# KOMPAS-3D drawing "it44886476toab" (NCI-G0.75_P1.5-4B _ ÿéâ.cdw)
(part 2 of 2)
  Кривая без истории:10773
  Кривая без истории:10774
  Кривая без истории:10775
  Кривая без истории:10776
  Кривая без истории:10777
  Кривая без истории:10778
  Кривая без истории:10779
  Кривая без истории:10780
  Кривая без истории:10781
  Кривая без истории:10782
  Кривая без истории:10783
  Кривая без истории:10784
  Кривая без истории:10785
  Кривая без истории:10786
  Кривая без истории:10787
  Кривая без истории:10788
  Кривая без истории:10789
  Кривая без истории:10790
  Кривая без истории:10791
  Кривая без истории:10792
  Кривая без истории:10793
  Кривая без истории:10794
  Кривая без истории:10795
  Кривая без истории:10796
  Кривая без истории:10797
  Кривая без истории:10798
  Кривая без истории:10799
  Кривая без истории:10800
  Кривая без истории:10801
  Кривая без истории:10802
  Кривая без истории:10803
  Кривая без истории:10804
  Кривая без истории:10805
  Кривая без истории:10806
  Кривая без истории:10807
  Кривая без истории:10808
  Кривая без истории:10809
  Кривая без истории:10810
  Кривая без истории:10811
  Кривая без истории:10812
  Кривая без истории:10813
  Кривая без истории:10814
  Кривая без истории:10815
  Кривая без истории:10816
  Кривая без истории:10817
  Кривая без истории:10818
  Кривая без истории:10819
  Кривая без истории:10820
  Кривая без истории:10821
  Кривая без истории:10822
  Кривая без истории:10823
  Кривая без истории:10824
  Кривая без истории:10825
  Кривая без истории:10826
  Кривая без истории:10827
  Кривая без истории:10828
  Кривая без истории:10829
  Кривая без истории:10830
  Кривая без истории:10831
  Кривая без истории:10832
  Кривая без истории:10833
  Кривая без истории:10834
  Кривая без истории:10835
  Кривая без истории:10836
  Кривая без истории:10837
  Кривая без истории:10838
  Кривая без истории:10839
  Кривая без истории:10840
  Кривая без истории:10841
  Кривая без истории:10842
  Кривая без истории:10843
  Кривая без истории:10844
  Кривая без истории:10845
  Кривая без истории:10846
  Кривая без истории:10847
  Кривая без истории:10848
  Кривая без истории:10849
  Кривая без истории:10850
  Кривая без истории:10851
  Кривая без истории:10852
  Кривая без истории:10853
  Кривая без истории:10854
  Кривая без истории:10855
  Кривая без истории:10856
  Кривая без истории:10857
  Кривая без истории:10858
  Кривая без истории:10859
  Кривая без истории:10860
  Кривая без истории:10861
  Кривая без истории:10862
  Кривая без истории:10863
  Кривая без истории:10864
  Кривая без истории:10865
  Кривая без истории:10866
  Кривая без истории:10867
  Кривая без истории:10868
  Кривая без истории:10869
  Кривая без истории:10870
  Кривая без истории:10871
  Кривая без истории:10872
  Кривая без истории:10873
  Кривая без истории:10874
  Кривая без истории:10875
  Кривая без истории:10876
  Кривая без истории:10877
  Кривая без истории:10878
  Кривая без истории:10879
  Кривая без истории:10880
  Кривая без истории:10881
  Кривая без истории:10882
  Кривая без истории:10883
  Кривая без истории:10884
  Кривая без истории:10885
  Кривая без истории:10886
  Кривая без истории:10887
  Кривая без истории:10888
  Кривая без истории:10889
  Кривая без истории:10890
  Кривая без истории:10891
  Кривая без истории:10892
  Кривая без истории:10893
  Кривая без истории:10894
  Кривая без истории:10895
  Кривая без истории:10896
  Кривая без истории:10897
  Кривая без истории:10898
  Кривая без истории:10899
  Кривая без истории:10900
  Кривая без истории:10901
  Кривая без истории:10902
  Кривая без истории:10903
  Кривая без истории:10904
  Кривая без истории:10905
  Кривая без истории:10906
  Кривая без истории:10907
  Кривая без истории:10908
  Кривая без истории:10909
  Кривая без истории:10910
  Кривая без истории:10911
  Кривая без истории:10912
  Кривая без истории:10913
  Кривая без истории:10914
  Кривая без истории:10915
  Кривая без истории:10916
  Кривая без истории:10917
  Кривая без истории:10918
  Кривая без истории:10919
  Кривая без истории:10920
  Кривая без истории:10921
  Кривая без истории:10922
  Кривая без истории:10923
  Кривая без истории:10924
  Кривая без истории:10925
  Кривая без истории:10926
  Кривая без истории:10927
  Кривая без истории:10928
  Кривая без истории:10929
  Кривая без истории:10930
  Кривая без истории:10931
  Кривая без истории:10932
  Кривая без истории:10933
  Кривая без истории:10934
  Кривая без истории:10935
  Кривая без истории:10936
  Кривая без истории:10937
  Кривая без истории:10938
  Кривая без истории:10939
  Кривая без истории:10940
  Кривая без истории:10941
  Кривая без истории:10942
  Кривая без истории:10943
  Кривая без истории:10944
  Кривая без истории:10945
  Кривая без истории:10946
  Кривая без истории:10947
  Кривая без истории:10948
  Кривая без истории:10949
  Кривая без истории:10950
  Кривая без истории:10951
  Кривая без истории:10952
  Кривая без истории:10953
  Кривая без истории:10954
  Кривая без истории:10955
  Кривая без истории:10956
  Кривая без истории:10957
  Кривая без истории:10958
  Кривая без истории:10959
  Кривая без истории:10960
  Кривая без истории:10961
  Кривая без истории:10962
  Кривая без истории:10963
  Кривая без истории:10964
  Кривая без истории:10965
  Кривая без истории:10966
  Кривая без истории:10967
  Кривая без истории:10968
  Кривая без истории:10969
  Кривая без истории:10970
  Кривая без истории:10971
  Кривая без истории:10972
  Кривая без истории:10973
  Кривая без истории:10974
  Кривая без истории:10975
  Кривая без истории:10976
  Кривая без истории:10977
  Кривая без истории:10978
  Кривая без истории:10979
  Кривая без истории:10980
  Кривая без истории:10981
  Кривая без истории:10982
  Кривая без истории:10983
  Кривая без истории:10984
  Кривая без истории:10985
  Кривая без истории:10986
  Кривая без истории:10987
  Кривая без истории:10988
  Кривая без истории:10989
  Кривая без истории:10990
  Кривая без истории:10991
  Кривая без истории:10992
  Кривая без истории:10993
  Кривая без истории:10994
  Кривая без истории:10995
  Кривая без истории:10996
  Кривая без истории:10997
  Кривая без истории:10998
  Кривая без истории:10999
  Кривая без истории:11000
  Кривая без истории:11001
  Кривая без истории:11002
  Кривая без истории:11003
  Кривая без истории:11004
  Кривая без истории:11005
  Кривая без истории:11006
  Кривая без истории:11007
  Кривая без истории:11008
  Кривая без истории:11009
  Кривая без истории:11010
  Кривая без истории:11011
  Кривая без истории:11012
  Кривая без истории:11013
  Кривая без истории:11014
  Кривая без истории:11015
  Кривая без истории:11016
  Кривая без истории:11017
  Кривая без истории:11018
  Кривая без истории:11019
  Кривая без истории:11020
  Кривая без истории:11021
  Кривая без истории:11022
  Кривая без истории:11023
  Кривая без истории:11024
  Кривая без истории:11025
  Кривая без истории:11026
  Кривая без истории:11027
  Кривая без истории:11028
  Кривая без истории:11029
  Кривая без истории:11030
  Кривая без истории:11031
  Кривая без истории:11032
  Кривая без истории:11033
  Кривая без истории:11034
  Кривая без истории:11035
  Кривая без истории:11036
  Кривая без истории:11037
  Кривая без истории:11038
  Кривая без истории:11039
  Кривая без истории:11040
  Кривая без истории:11041
  Кривая без истории:11042
  Кривая без истории:11043
  Кривая без истории:11044
  Кривая без истории:11045
  Кривая без истории:11046
  Кривая без истории:11047
  Кривая без истории:11048
  Кривая без истории:11049
  Кривая без истории:11050
  Кривая без истории:11051
  Кривая без истории:11052
  Кривая без истории:11053
  Кривая без истории:11054
  Кривая без истории:11055
  Кривая без истории:11056
  Кривая без истории:11057
  Кривая без истории:11058
  Кривая без истории:11059
  Кривая без истории:11060
  Кривая без истории:11061
  Кривая без истории:11062
  Кривая без истории:11063
  Кривая без истории:11064
  Кривая без истории:11065
  Кривая без истории:11066
  Кривая без истории:11067
  Кривая без истории:11068
  Кривая без истории:11069
  Кривая без истории:11070
  Кривая без истории:11071
  Кривая без истории:11072
  Кривая без истории:11073
  Кривая без истории:11074
  Кривая без истории:11075
  Кривая без истории:11076
  Кривая без истории:11077
  Кривая без истории:11078
  Кривая без истории:11079
  Кривая без истории:11080
  Кривая без истории:11081
  Кривая без истории:11082
  Кривая без истории:11083
  Кривая без истории:11084
  Кривая без истории:11085
  Кривая без истории:11086
  Кривая без истории:11087
  Кривая без истории:11088
  Кривая без истории:11089
  Кривая без истории:11090
  Кривая без истории:11091
  Кривая без истории:11092
  Кривая без истории:11093
  Кривая без истории:11094
  Кривая без истории:11095
  Кривая без истории:11096
  Кривая без истории:11097
  Кривая без истории:11098
  Кривая без истории:11099
  Кривая без истории:11100
  Кривая без истории:11101
  Кривая без истории:11102
  Кривая без истории:11103
  Кривая без истории:11104
  Кривая без истории:11105
  Кривая без истории:11106
  Кривая без истории:11107
  Кривая без истории:11108
  Кривая без истории:11109
  Кривая без истории:11110
  Кривая без истории:11111
  Кривая без истории:11112
  Кривая без истории:11113
  Кривая без истории:11114
  Кривая без истории:11115
  Кривая без истории:11116
  Кривая без истории:11117
  Кривая без истории:11118
  Кривая без истории:11119
  Кривая без истории:11120
  Кривая без истории:11121
  Кривая без истории:11122
  Кривая без истории:11123
  Кривая без истории:11124
  Кривая без истории:11125
  Кривая без истории:11126
  Кривая без истории:11127
  Кривая без истории:11128
  Кривая без истории:11129
  Кривая без истории:11130
  Кривая без истории:11131
  Кривая без истории:11132
  Кривая без истории:11133
  Кривая без истории:11134
  Кривая без истории:11135
  Кривая без истории:11136
  Кривая без истории:11137
  Кривая без истории:11138
  Кривая без истории:11139
  Кривая без истории:11140
  Кривая без истории:11141
  Кривая без истории:11142
  Кривая без истории:11143
  Кривая без истории:11144
  Кривая без истории:11145
  Кривая без истории:11146
  Кривая без истории:11147
  Кривая без истории:11148
  Кривая без истории:11149
  Кривая без истории:11150
  Кривая без истории:11151
  Кривая без истории:11152
  Кривая без истории:11153
  Кривая без истории:11154
  Кривая без истории:11155
  Кривая без истории:11156
  Кривая без истории:11157
  Кривая без истории:11158
  Кривая без истории:11159
  Кривая без истории:11160
  Кривая без истории:11161
  Кривая без истории:11162
  Кривая без истории:11163
  Кривая без истории:11164
  Кривая без истории:11165
  Кривая без истории:11166
  Кривая без истории:11167
  Кривая без истории:11168
  Кривая без истории:11169
  Кривая без истории:11170
  Кривая без истории:11171
  Кривая без истории:11172
  Кривая без истории:11173
  Кривая без истории:11174
  Кривая без истории:11175
  Кривая без истории:11176
  Кривая без истории:11177
  Кривая без истории:11178
  Кривая без истории:11179
  Кривая без истории:11180
  Кривая без истории:11181
  Кривая без истории:11182
  Кривая без истории:11183
  Кривая без истории:11184
  Кривая без истории:11185
  Кривая без истории:11186
  Кривая без истории:11187
  Кривая без истории:11188
  Кривая без истории:11189
  Кривая без истории:11190
  Кривая без истории:11191
  Кривая без истории:11192
  Кривая без истории:11193
  Кривая без истории:11194
  Кривая без истории:11195
  Кривая без истории:11196
  Кривая без истории:11197
  Кривая без истории:11198
  Кривая без истории:11199
  Кривая без истории:11200
  Кривая без истории:11201
  Кривая без истории:11202
  Кривая без истории:11203
  Кривая без истории:11204
  Кривая без истории:11205
  Кривая без истории:11206
  Кривая без истории:11207
  Кривая без истории:11208
  Кривая без истории:11209
  Кривая без истории:11210
  Кривая без истории:11211
  Кривая без истории:11212
  Кривая без истории:11213
  Кривая без истории:11214
  Кривая без истории:11215
  Кривая без истории:11216
  Кривая без истории:11217
  Кривая без истории:11218
  Кривая без истории:11219
  Кривая без истории:11220
  Кривая без истории:11221
  Кривая без истории:11222
  Кривая без истории:11223
  Кривая без истории:11224
  Кривая без истории:11225
  Кривая без истории:11226
  Кривая без истории:11227
  Кривая без истории:11228
  Кривая без истории:11229
  Кривая без истории:11230
  Кривая без истории:11231
  Кривая без истории:11232
  Кривая без истории:11233
  Кривая без истории:11234
  Кривая без истории:11235
  Кривая без истории:11236
  Кривая без истории:11237
  Кривая без истории:11238
  Кривая без истории:11239
  Кривая без истории:11240
  Кривая без истории:11241
  Кривая без истории:11242
  Кривая без истории:11243
  Кривая без истории:11244
  Кривая без истории:11245
  Кривая без истории:11246
  Кривая без истории:11247
  Кривая без истории:11248
  Кривая без истории:11249
  Кривая без истории:11250
  Кривая без истории:11251
  Кривая без истории:11252
  Кривая без истории:11253
  Кривая без истории:11254
  Кривая без истории:11255
  Кривая без истории:11256
  Кривая без истории:11257
  Кривая без истории:11258
  Кривая без истории:11259
  Кривая без истории:11260
  Кривая без истории:11261
  Кривая без истории:11262
  Кривая без истории:11263
  Кривая без истории:11264
  Кривая без истории:11265
  Кривая без истории:11266
  Кривая без истории:11267
  Кривая без истории:11268
  Кривая без истории:11269
  Кривая без истории:11270
  Кривая без истории:11271
  Кривая без истории:11272
  Кривая без истории:11273
  Кривая без истории:11274
  Кривая без истории:11275
  Кривая без истории:11276
  Кривая без истории:11277
  Кривая без истории:11278
  Кривая без истории:11279
  Кривая без истории:11280
  Кривая без истории:11281
  Кривая без истории:11282
  Кривая без истории:11283
  Кривая без истории:11284
  Кривая без истории:11285
  Кривая без истории:11286
  Кривая без истории:11287
  Кривая без истории:11288
  Кривая без истории:11289
  Кривая без истории:11290
  Кривая без истории:11291
  Кривая без истории:11292
  Кривая без истории:11293
  Кривая без истории:11294
  Кривая без истории:11295
  Кривая без истории:11296
  Кривая без истории:11297
  Кривая без истории:11298
  Кривая без истории:11299
  Кривая без истории:11300
  Кривая без истории:11301
  Кривая без истории:11302
  Кривая без истории:11303
  Кривая без истории:11304
  Кривая без истории:11305
  Кривая без истории:11306
  Кривая без истории:11307
  Кривая без истории:11308
  Кривая без истории:11309
  Кривая без истории:11310
  Кривая без истории:11311
  Кривая без истории:11312
  Кривая без истории:11313
  Кривая без истории:11314
  Кривая без истории:11315
  Кривая без истории:11316
  Кривая без истории:11317
  Кривая без истории:11318
  Кривая без истории:11319
  Кривая без истории:11320
  Кривая без истории:11321
  Кривая без истории:11322
  Кривая без истории:11323
  Кривая без истории:11324
  Кривая без истории:11325
  Кривая без истории:11326
  Кривая без истории:11327
  Кривая без истории:11328
  Кривая без истории:11329
  Кривая без истории:11330
  Кривая без истории:11331
  Кривая без истории:11332
  Кривая без истории:11333
  Кривая без истории:11334
  Кривая без истории:11335
  Кривая без истории:11336
  Кривая без истории:11337
  Кривая без истории:11338
  Кривая без истории:11339
  Кривая без истории:11340
  Кривая без истории:11341
  Кривая без истории:11342
  Кривая без истории:11343
  Кривая без истории:11344
  Кривая без истории:11345
  Кривая без истории:11346
  Кривая без истории:11347
  Кривая без истории:11348
  Кривая без истории:11349
  Кривая без истории:11350
  Кривая без истории:11351
  Кривая без истории:11352
  Кривая без истории:11353
  Кривая без истории:11354
  Кривая без истории:11355
  Кривая без истории:11356
  Кривая без истории:11357
  Кривая без истории:11358
  Кривая без истории:11359
  Кривая без истории:11360
  Кривая без истории:11361
  Кривая без истории:11362
  Кривая без истории:11363
  Кривая без истории:11364
  Кривая без истории:11365
  Кривая без истории:11366
  Кривая без истории:11367
  Кривая без истории:11368
  Кривая без истории:11369
  Кривая без истории:11370
  Кривая без истории:11371
  Кривая без истории:11372
  Кривая без истории:11373
  Кривая без истории:11374
  Кривая без истории:11375
  Кривая без истории:11376
  Кривая без истории:11377
  Кривая без истории:11378
  Кривая без истории:11379
  Кривая без истории:11380
  Кривая без истории:11381
  Кривая без истории:11382
  Кривая без истории:11383
  Кривая без истории:11384
  Кривая без истории:11385
  Кривая без истории:11386
  Кривая без истории:11387
  Кривая без истории:11388
  Кривая без истории:11389
  Кривая без истории:11390
  Кривая без истории:11391
  Кривая без истории:11392
  Кривая без истории:11393
  Кривая без истории:11394
  Кривая без истории:11395
  Кривая без истории:11396
  Кривая без истории:11397
  Кривая без истории:11398
  Кривая без истории:11399
  Кривая без истории:11400
  Кривая без истории:11401
  Кривая без истории:11402
  Кривая без истории:11403
  Кривая без истории:11404
  Кривая без истории:11405
  Кривая без истории:11406
  Кривая без истории:11407
  Кривая без истории:11408
  Кривая без истории:11409
  Кривая без истории:11410
  Кривая без истории:11411
  Кривая без истории:11412
  Кривая без истории:11413
  Кривая без истории:11414
  Кривая без истории:11415
  Кривая без истории:11416
  Кривая без истории:11417
  Кривая без истории:11418
  Кривая без истории:11419
  Кривая без истории:11420
  Кривая без истории:11421
  Кривая без истории:11422
  Кривая без истории:11423
  Кривая без истории:11424
  Кривая без истории:11425
  Кривая без истории:11426
  Кривая без истории:11427
  Кривая без истории:11428
  Кривая без истории:11429
  Кривая без истории:11430
  Кривая без истории:11431
  Кривая без истории:11432
  Кривая без истории:11433
  Кривая без истории:11434
  Кривая без истории:11435
  Кривая без истории:11436
  Кривая без истории:11437
  Кривая без истории:11438
  Кривая без истории:11439
  Кривая без истории:11440
  Кривая без истории:11441
  Кривая без истории:11442
  Кривая без истории:11443
  Кривая без истории:11444
  Кривая без истории:11445
  Кривая без истории:11446
  Кривая без истории:11447
  Кривая без истории:11448
  Кривая без истории:11449
  Кривая без истории:11450
  Кривая без истории:11451
  Кривая без истории:11452
  Кривая без истории:11453
  Кривая без истории:11454
  Кривая без истории:11455
  Кривая без истории:11456
  Кривая без истории:11457
  Кривая без истории:11458
  Кривая без истории:11459
  Кривая без истории:11460
  Кривая без истории:11461
  Кривая без истории:11462
  Кривая без истории:11463
  Кривая без истории:11464
  Кривая без истории:11465
  Кривая без истории:11466
  Кривая без истории:11467
  Кривая без истории:11468
  Кривая без истории:11469
  Кривая без истории:11470
  Кривая без истории:11471
  Кривая без истории:11472
  Кривая без истории:11473
  Кривая без истории:11474
  Кривая без истории:11475
  Кривая без истории:11476
  Кривая без истории:11477
  Кривая без истории:11478
  Кривая без истории:11479
  Кривая без истории:11480
  Кривая без истории:11481
  Кривая без истории:11482
  Кривая без истории:11483
  Кривая без истории:11484
  Кривая без истории:11485
  Кривая без истории:11486
  Кривая без истории:11487
  Кривая без истории:11488
  Кривая без истории:11489
  Кривая без истории:11490
  Кривая без истории:11491
  Кривая без истории:11492
  Кривая без истории:11493
  Кривая без истории:11494
  Кривая без истории:11495
  Кривая без истории:11496
  Кривая без истории:11497
  Кривая без истории:11498
  Кривая без истории:11499
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Dimensions and other numbers on the sheet: 1:1; 1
